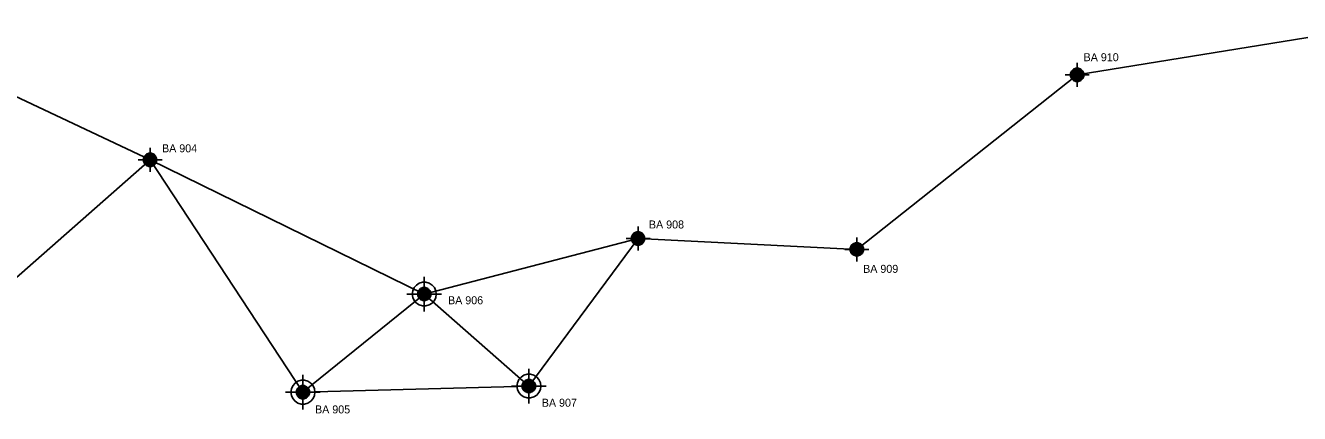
# Model space of a CAD drawing. Extents: x -346533 to -339969, y -1273090 to -1271585.
# Drawn here: x -344688 to -343494, y -1272964 to -1272600 of the extents above; entities that cross this region are included whole.
import ezdxf

# ---------------------------------------------------------------- set-up
doc = ezdxf.new("R2010")
doc.units = 0
for name, color, linetype in [('BP_11', 7, 'Continuous'), ('BP_12', 7, 'Continuous'), ('BP_14', 7, 'Continuous')]:
    doc.layers.add(name, color=color, linetype=linetype)

msp = doc.modelspace()

# ---------------------------------------------------------------- linework, layer by layer
at = {"layer": 'BP_11'}
for points in [[(-343702.54, -1272658), (-343702.54, -1272651.65), (-343702.54, -1272645.3), (-343702.54, -1272638.95), (-343702.54, -1272635.5)], [(-343713.79, -1272646.75), (-343707.44, -1272646.75), (-343701.09, -1272646.75), (-343694.74, -1272646.75), (-343691.29, -1272646.75)], [(-343702.54, -1272640.6), (-343701.34, -1272640.6), (-343699.09, -1272641.55), (-343697.39, -1272643.25), (-343696.44, -1272645.5), (-343696.44, -1272647.95), (-343697.39, -1272650.2), (-343699.09, -1272651.9), (-343701.34, -1272652.85), (-343703.79, -1272652.85), (-343706.04, -1272651.9), (-343707.74, -1272650.2), (-343708.69, -1272647.95), (-343708.69, -1272645.5), (-343707.74, -1272643.25), (-343706.04, -1272641.55), (-343703.79, -1272640.6), (-343702.59, -1272640.6), (-343700.79, -1272640.95), (-343704.39, -1272640.95), (-343705.19, -1272641.35), (-343699.99, -1272641.35), (-343699.19, -1272641.75), (-343705.54, -1272641.75), (-343705.99, -1272641.75), (-343706.39, -1272642.15), (-343700.04, -1272642.15), (-343698.79, -1272642.15), (-343698.39, -1272642.55), (-343704.74, -1272642.55), (-343706.79, -1272642.55), (-343707.19, -1272642.95), (-343700.84, -1272642.95), (-343697.99, -1272642.95), (-343697.59, -1272643.35), (-343703.94, -1272643.35), (-343707.59, -1272643.35), (-343707.59, -1272643.75), (-343701.24, -1272643.75), (-343697.59, -1272643.75), (-343697.19, -1272644.15), (-343703.54, -1272644.15), (-343707.99, -1272644.15), (-343707.99, -1272644.55), (-343701.64, -1272644.55), (-343697.19, -1272644.55), (-343696.79, -1272644.95), (-343703.14, -1272644.95), (-343708.39, -1272644.95), (-343708.39, -1272645.35), (-343702.04, -1272645.35), (-343696.79, -1272645.35), (-343696.79, -1272645.75), (-343703.14, -1272645.75), (-343708.39, -1272645.75), (-343708.39, -1272646.15), (-343702.04, -1272646.15), (-343696.79, -1272646.15), (-343696.79, -1272646.55), (-343703.14, -1272646.55), (-343708.39, -1272646.55), (-343708.39, -1272646.95), (-343702.04, -1272646.95), (-343696.79, -1272646.95), (-343696.79, -1272647.35), (-343703.14, -1272647.35), (-343708.39, -1272647.35), (-343708.39, -1272647.75), (-343702.04, -1272647.75), (-343696.79, -1272647.75), (-343696.79, -1272648.15), (-343703.14, -1272648.15), (-343708.39, -1272648.15), (-343708.39, -1272648.55), (-343702.04, -1272648.55), (-343696.79, -1272648.55), (-343697.19, -1272648.95), (-343703.54, -1272648.95), (-343707.99, -1272648.95), (-343707.99, -1272649.35), (-343701.64, -1272649.35), (-343697.19, -1272649.35), (-343697.59, -1272649.75), (-343703.94, -1272649.75), (-343707.59, -1272649.75), (-343707.59, -1272650.15), (-343701.24, -1272650.15), (-343697.59, -1272650.15), (-343697.99, -1272650.55), (-343704.34, -1272650.55), (-343707.19, -1272650.55), (-343706.79, -1272650.95), (-343700.44, -1272650.95), (-343698.39, -1272650.95), (-343698.79, -1272651.35), (-343705.14, -1272651.35), (-343706.39, -1272651.35), (-343705.99, -1272651.75), (-343699.64, -1272651.75), (-343699.19, -1272651.75)], [(-343699.19, -1272651.75), (-343699.99, -1272652.15), (-343705.19, -1272652.15), (-343704.39, -1272652.55), (-343700.79, -1272652.55)], [(-344571.36, -1272720.27), (-344570.16, -1272720.27), (-344567.91, -1272721.22), (-344566.21, -1272722.92), (-344565.26, -1272725.17), (-344565.26, -1272727.62), (-344566.21, -1272729.87), (-344567.91, -1272731.57), (-344570.16, -1272732.52), (-344572.61, -1272732.52), (-344574.86, -1272731.57), (-344576.56, -1272729.87), (-344577.51, -1272727.62), (-344577.51, -1272725.17), (-344576.56, -1272722.92), (-344574.86, -1272721.22), (-344572.61, -1272720.27), (-344571.41, -1272720.27), (-344569.61, -1272720.62), (-344573.21, -1272720.62), (-344574.01, -1272721.02), (-344568.81, -1272721.02), (-344568.01, -1272721.42), (-344574.36, -1272721.42), (-344574.81, -1272721.42), (-344575.21, -1272721.82), (-344568.86, -1272721.82), (-344567.61, -1272721.82), (-344567.21, -1272722.22), (-344573.56, -1272722.22), (-344575.61, -1272722.22), (-344576.01, -1272722.62), (-344569.66, -1272722.62), (-344566.81, -1272722.62), (-344566.41, -1272723.02), (-344572.76, -1272723.02), (-344576.41, -1272723.02), (-344576.41, -1272723.42), (-344570.06, -1272723.42), (-344566.41, -1272723.42), (-344566.01, -1272723.82), (-344572.36, -1272723.82), (-344576.81, -1272723.82), (-344576.81, -1272724.22), (-344570.46, -1272724.22), (-344566.01, -1272724.22), (-344565.61, -1272724.62), (-344571.96, -1272724.62), (-344577.21, -1272724.62), (-344577.21, -1272725.02), (-344570.86, -1272725.02), (-344565.61, -1272725.02), (-344565.61, -1272725.42), (-344571.96, -1272725.42), (-344577.21, -1272725.42), (-344577.21, -1272725.82), (-344570.86, -1272725.82), (-344565.61, -1272725.82), (-344565.61, -1272726.22), (-344571.96, -1272726.22), (-344577.21, -1272726.22), (-344577.21, -1272726.62), (-344570.86, -1272726.62), (-344565.61, -1272726.62), (-344565.61, -1272727.02), (-344571.96, -1272727.02), (-344577.21, -1272727.02), (-344577.21, -1272727.42), (-344570.86, -1272727.42), (-344565.61, -1272727.42), (-344565.61, -1272727.82), (-344571.96, -1272727.82), (-344577.21, -1272727.82), (-344577.21, -1272728.22), (-344570.86, -1272728.22), (-344565.61, -1272728.22), (-344566.01, -1272728.62), (-344572.36, -1272728.62), (-344576.81, -1272728.62), (-344576.81, -1272729.02), (-344570.46, -1272729.02), (-344566.01, -1272729.02), (-344566.41, -1272729.42), (-344572.76, -1272729.42), (-344576.41, -1272729.42), (-344576.41, -1272729.82), (-344570.06, -1272729.82), (-344566.41, -1272729.82), (-344566.81, -1272730.22), (-344573.16, -1272730.22), (-344576.01, -1272730.22), (-344575.61, -1272730.62), (-344569.26, -1272730.62), (-344567.21, -1272730.62), (-344567.61, -1272731.02), (-344573.96, -1272731.02), (-344575.21, -1272731.02), (-344574.81, -1272731.42), (-344568.46, -1272731.42), (-344568.01, -1272731.42)], [(-344571.36, -1272737.67), (-344571.36, -1272731.32), (-344571.36, -1272724.97), (-344571.36, -1272718.62), (-344571.36, -1272715.17)], [(-344582.61, -1272726.42), (-344576.26, -1272726.42), (-344569.91, -1272726.42), (-344563.56, -1272726.42), (-344560.11, -1272726.42)], [(-344568.01, -1272731.42), (-344568.81, -1272731.82), (-344574.01, -1272731.82), (-344573.21, -1272732.22), (-344569.61, -1272732.22)], [(-344114.12, -1272811.38), (-344114.12, -1272805.03), (-344114.12, -1272798.68), (-344114.12, -1272792.33), (-344114.12, -1272788.88)], [(-344125.37, -1272800.13), (-344119.02, -1272800.13), (-344112.67, -1272800.13), (-344106.32, -1272800.13), (-344102.87, -1272800.13)], [(-344114.12, -1272793.98), (-344112.92, -1272793.98), (-344110.67, -1272794.93), (-344108.97, -1272796.63), (-344108.02, -1272798.88), (-344108.02, -1272801.33), (-344108.97, -1272803.58), (-344110.67, -1272805.28), (-344112.92, -1272806.23), (-344115.37, -1272806.23), (-344117.62, -1272805.28), (-344119.32, -1272803.58), (-344120.27, -1272801.33), (-344120.27, -1272798.88), (-344119.32, -1272796.63), (-344117.62, -1272794.93), (-344115.37, -1272793.98), (-344114.17, -1272793.98), (-344112.37, -1272794.33), (-344115.97, -1272794.33), (-344116.77, -1272794.73), (-344111.57, -1272794.73), (-344110.77, -1272795.13), (-344117.12, -1272795.13), (-344117.57, -1272795.13), (-344117.97, -1272795.53), (-344111.62, -1272795.53), (-344110.37, -1272795.53), (-344109.97, -1272795.93), (-344116.32, -1272795.93), (-344118.37, -1272795.93), (-344118.77, -1272796.33), (-344112.42, -1272796.33), (-344109.57, -1272796.33), (-344109.17, -1272796.73), (-344115.52, -1272796.73), (-344119.17, -1272796.73), (-344119.17, -1272797.13), (-344112.82, -1272797.13), (-344109.17, -1272797.13), (-344108.77, -1272797.53), (-344115.12, -1272797.53), (-344119.57, -1272797.53), (-344119.57, -1272797.93), (-344113.22, -1272797.93), (-344108.77, -1272797.93), (-344108.37, -1272798.33), (-344114.72, -1272798.33), (-344119.97, -1272798.33), (-344119.97, -1272798.73), (-344113.62, -1272798.73), (-344108.37, -1272798.73), (-344108.37, -1272799.13), (-344114.72, -1272799.13), (-344119.97, -1272799.13), (-344119.97, -1272799.53), (-344113.62, -1272799.53), (-344108.37, -1272799.53), (-344108.37, -1272799.93), (-344114.72, -1272799.93), (-344119.97, -1272799.93), (-344119.97, -1272800.33), (-344113.62, -1272800.33), (-344108.37, -1272800.33), (-344108.37, -1272800.73), (-344114.72, -1272800.73), (-344119.97, -1272800.73), (-344119.97, -1272801.13), (-344113.62, -1272801.13), (-344108.37, -1272801.13), (-344108.37, -1272801.53), (-344114.72, -1272801.53), (-344119.97, -1272801.53), (-344119.97, -1272801.93), (-344113.62, -1272801.93), (-344108.37, -1272801.93), (-344108.77, -1272802.33), (-344115.12, -1272802.33), (-344119.57, -1272802.33), (-344119.57, -1272802.73), (-344113.22, -1272802.73), (-344108.77, -1272802.73), (-344109.17, -1272803.13), (-344115.52, -1272803.13), (-344119.17, -1272803.13), (-344119.17, -1272803.53), (-344112.82, -1272803.53), (-344109.17, -1272803.53), (-344109.57, -1272803.93), (-344115.92, -1272803.93), (-344118.77, -1272803.93), (-344118.37, -1272804.33), (-344112.02, -1272804.33), (-344109.97, -1272804.33), (-344110.37, -1272804.73), (-344116.72, -1272804.73), (-344117.97, -1272804.73), (-344117.57, -1272805.13), (-344111.22, -1272805.13), (-344110.77, -1272805.13)], [(-344110.77, -1272805.13), (-344111.57, -1272805.53), (-344116.77, -1272805.53), (-344115.97, -1272805.93), (-344112.37, -1272805.93)], [(-343909.01, -1272804.12), (-343907.81, -1272804.12), (-343905.56, -1272805.07), (-343903.86, -1272806.77), (-343902.91, -1272809.02), (-343902.91, -1272811.47), (-343903.86, -1272813.72), (-343905.56, -1272815.42), (-343907.81, -1272816.37), (-343910.26, -1272816.37), (-343912.51, -1272815.42), (-343914.21, -1272813.72), (-343915.16, -1272811.47), (-343915.16, -1272809.02), (-343914.21, -1272806.77), (-343912.51, -1272805.07), (-343910.26, -1272804.12), (-343909.06, -1272804.12), (-343907.26, -1272804.47), (-343910.86, -1272804.47), (-343911.66, -1272804.87), (-343906.46, -1272804.87), (-343905.66, -1272805.27), (-343912.01, -1272805.27), (-343912.46, -1272805.27), (-343912.86, -1272805.67), (-343906.51, -1272805.67), (-343905.26, -1272805.67), (-343904.86, -1272806.07), (-343911.21, -1272806.07), (-343913.26, -1272806.07), (-343913.66, -1272806.47), (-343907.31, -1272806.47), (-343904.46, -1272806.47), (-343904.06, -1272806.87), (-343910.41, -1272806.87), (-343914.06, -1272806.87), (-343914.06, -1272807.27), (-343907.71, -1272807.27), (-343904.06, -1272807.27), (-343903.66, -1272807.67), (-343910.01, -1272807.67), (-343914.46, -1272807.67), (-343914.46, -1272808.07), (-343908.11, -1272808.07), (-343903.66, -1272808.07), (-343903.26, -1272808.47), (-343909.61, -1272808.47), (-343914.86, -1272808.47), (-343914.86, -1272808.87), (-343908.51, -1272808.87), (-343903.26, -1272808.87), (-343903.26, -1272809.27), (-343909.61, -1272809.27), (-343914.86, -1272809.27), (-343914.86, -1272809.67), (-343908.51, -1272809.67), (-343903.26, -1272809.67), (-343903.26, -1272810.07), (-343909.61, -1272810.07), (-343914.86, -1272810.07), (-343914.86, -1272810.47), (-343908.51, -1272810.47), (-343903.26, -1272810.47), (-343903.26, -1272810.87), (-343909.61, -1272810.87), (-343914.86, -1272810.87), (-343914.86, -1272811.27), (-343908.51, -1272811.27), (-343903.26, -1272811.27), (-343903.26, -1272811.67), (-343909.61, -1272811.67), (-343914.86, -1272811.67), (-343914.86, -1272812.07), (-343908.51, -1272812.07), (-343903.26, -1272812.07), (-343903.66, -1272812.47), (-343910.01, -1272812.47), (-343914.46, -1272812.47), (-343914.46, -1272812.87), (-343908.11, -1272812.87), (-343903.66, -1272812.87), (-343904.06, -1272813.27), (-343910.41, -1272813.27), (-343914.06, -1272813.27), (-343914.06, -1272813.67), (-343907.71, -1272813.67), (-343904.06, -1272813.67), (-343904.46, -1272814.07), (-343910.81, -1272814.07), (-343913.66, -1272814.07), (-343913.26, -1272814.47), (-343906.91, -1272814.47), (-343904.86, -1272814.47), (-343905.26, -1272814.87), (-343911.61, -1272814.87), (-343912.86, -1272814.87), (-343912.46, -1272815.27), (-343906.11, -1272815.27), (-343905.66, -1272815.27)], [(-343909.01, -1272821.52), (-343909.01, -1272815.17), (-343909.01, -1272808.82), (-343909.01, -1272802.47), (-343909.01, -1272799.02)], [(-343920.26, -1272810.27), (-343913.91, -1272810.27), (-343907.56, -1272810.27), (-343901.21, -1272810.27), (-343897.76, -1272810.27)], [(-343905.66, -1272815.27), (-343906.46, -1272815.67), (-343911.66, -1272815.67), (-343910.86, -1272816.07), (-343907.26, -1272816.07)], [(-344314.42, -1272868.49), (-344314.42, -1272862.14), (-344314.42, -1272855.79), (-344314.42, -1272849.44), (-344314.42, -1272843.09), (-344314.42, -1272836.74), (-344314.42, -1272835.99)], [(-344330.67, -1272852.24), (-344324.32, -1272852.24), (-344317.97, -1272852.24), (-344311.62, -1272852.24), (-344305.27, -1272852.24), (-344298.92, -1272852.24), (-344298.17, -1272852.24)], [(-344314.42, -1272846.09), (-344313.22, -1272846.09), (-344310.97, -1272847.04), (-344309.27, -1272848.74), (-344308.32, -1272850.99), (-344308.32, -1272853.44), (-344309.27, -1272855.69), (-344310.97, -1272857.39), (-344313.22, -1272858.34), (-344315.67, -1272858.34), (-344317.92, -1272857.39), (-344319.62, -1272855.69), (-344320.57, -1272853.44), (-344320.57, -1272850.99), (-344319.62, -1272848.74), (-344317.92, -1272847.04), (-344315.67, -1272846.09), (-344314.47, -1272846.09), (-344312.67, -1272846.44), (-344316.27, -1272846.44), (-344317.07, -1272846.84), (-344311.87, -1272846.84), (-344311.07, -1272847.24), (-344317.42, -1272847.24), (-344317.87, -1272847.24), (-344318.27, -1272847.64), (-344311.92, -1272847.64), (-344310.67, -1272847.64), (-344310.27, -1272848.04), (-344316.62, -1272848.04), (-344318.67, -1272848.04), (-344319.07, -1272848.44), (-344312.72, -1272848.44), (-344309.87, -1272848.44), (-344309.47, -1272848.84), (-344315.82, -1272848.84), (-344319.47, -1272848.84), (-344319.47, -1272849.24), (-344313.12, -1272849.24), (-344309.47, -1272849.24), (-344309.07, -1272849.64), (-344315.42, -1272849.64), (-344319.87, -1272849.64), (-344319.87, -1272850.04), (-344313.52, -1272850.04), (-344309.07, -1272850.04), (-344309.07, -1272850.44), (-344315.42, -1272850.44), (-344319.87, -1272850.44), (-344320.27, -1272850.84), (-344313.92, -1272850.84), (-344308.67, -1272850.84), (-344308.67, -1272851.24), (-344315.02, -1272851.24), (-344320.27, -1272851.24), (-344320.27, -1272851.64), (-344313.92, -1272851.64), (-344308.67, -1272851.64), (-344308.67, -1272852.04), (-344315.02, -1272852.04), (-344320.27, -1272852.04), (-344320.27, -1272852.44), (-344313.92, -1272852.44), (-344308.67, -1272852.44), (-344308.67, -1272852.84), (-344315.02, -1272852.84), (-344320.27, -1272852.84), (-344320.27, -1272853.24), (-344313.92, -1272853.24), (-344308.67, -1272853.24), (-344308.67, -1272853.64), (-344315.02, -1272853.64), (-344320.27, -1272853.64), (-344320.27, -1272854.04), (-344313.92, -1272854.04), (-344308.67, -1272854.04), (-344309.07, -1272854.44), (-344315.42, -1272854.44), (-344319.87, -1272854.44), (-344319.87, -1272854.84), (-344313.52, -1272854.84), (-344309.07, -1272854.84), (-344309.47, -1272855.24), (-344315.82, -1272855.24), (-344319.47, -1272855.24), (-344319.47, -1272855.64), (-344313.12, -1272855.64), (-344309.47, -1272855.64), (-344309.87, -1272856.04), (-344316.22, -1272856.04), (-344319.07, -1272856.04), (-344318.67, -1272856.44), (-344312.32, -1272856.44), (-344310.27, -1272856.44), (-344310.67, -1272856.84), (-344317.02, -1272856.84), (-344318.27, -1272856.84), (-344317.87, -1272857.24), (-344311.52, -1272857.24), (-344311.07, -1272857.24)], [(-344311.07, -1272857.24), (-344311.87, -1272857.64), (-344317.07, -1272857.64), (-344316.27, -1272858.04), (-344312.67, -1272858.04)], [(-344216.4, -1272954.74), (-344216.4, -1272948.39), (-344216.4, -1272942.04), (-344216.4, -1272935.69), (-344216.4, -1272929.34), (-344216.4, -1272922.99), (-344216.4, -1272922.24)], [(-344428.13, -1272960.43), (-344428.13, -1272954.08), (-344428.13, -1272947.73), (-344428.13, -1272941.38), (-344428.13, -1272935.03), (-344428.13, -1272928.68), (-344428.13, -1272927.93)], [(-344216.4, -1272932.34), (-344215.2, -1272932.34), (-344212.95, -1272933.29), (-344211.25, -1272934.99), (-344210.3, -1272937.24), (-344210.3, -1272939.69), (-344211.25, -1272941.94), (-344212.95, -1272943.64), (-344215.2, -1272944.59), (-344217.65, -1272944.59), (-344219.9, -1272943.64), (-344221.6, -1272941.94), (-344222.55, -1272939.69), (-344222.55, -1272937.24), (-344221.6, -1272934.99), (-344219.9, -1272933.29), (-344217.65, -1272932.34), (-344216.45, -1272932.34), (-344214.65, -1272932.69), (-344218.25, -1272932.69), (-344219.05, -1272933.09), (-344213.85, -1272933.09), (-344213.05, -1272933.49), (-344219.4, -1272933.49), (-344219.85, -1272933.49), (-344220.25, -1272933.89), (-344213.9, -1272933.89), (-344212.65, -1272933.89), (-344212.25, -1272934.29), (-344218.6, -1272934.29), (-344220.65, -1272934.29), (-344221.05, -1272934.69), (-344214.7, -1272934.69), (-344211.85, -1272934.69), (-344211.45, -1272935.09), (-344217.8, -1272935.09), (-344221.45, -1272935.09), (-344221.45, -1272935.49), (-344215.1, -1272935.49), (-344211.45, -1272935.49), (-344211.05, -1272935.89), (-344217.4, -1272935.89), (-344221.85, -1272935.89), (-344221.85, -1272936.29), (-344215.5, -1272936.29), (-344211.05, -1272936.29), (-344211.05, -1272936.69), (-344217.4, -1272936.69), (-344221.85, -1272936.69), (-344222.25, -1272937.09), (-344215.9, -1272937.09), (-344210.65, -1272937.09), (-344210.65, -1272937.49), (-344217, -1272937.49), (-344222.25, -1272937.49), (-344222.25, -1272937.89), (-344215.9, -1272937.89), (-344210.65, -1272937.89), (-344210.65, -1272938.29), (-344217, -1272938.29), (-344222.25, -1272938.29), (-344222.25, -1272938.69), (-344215.9, -1272938.69), (-344210.65, -1272938.69), (-344210.65, -1272939.09), (-344217, -1272939.09), (-344222.25, -1272939.09), (-344222.25, -1272939.49), (-344215.9, -1272939.49), (-344210.65, -1272939.49), (-344210.65, -1272939.89), (-344217, -1272939.89), (-344222.25, -1272939.89), (-344222.25, -1272940.29), (-344215.9, -1272940.29), (-344210.65, -1272940.29), (-344211.05, -1272940.69), (-344217.4, -1272940.69), (-344221.85, -1272940.69), (-344221.85, -1272941.09), (-344215.5, -1272941.09), (-344211.05, -1272941.09), (-344211.45, -1272941.49), (-344217.8, -1272941.49), (-344221.45, -1272941.49), (-344221.45, -1272941.89), (-344215.1, -1272941.89), (-344211.45, -1272941.89), (-344211.85, -1272942.29), (-344218.2, -1272942.29), (-344221.05, -1272942.29), (-344220.65, -1272942.69), (-344214.3, -1272942.69), (-344212.25, -1272942.69), (-344212.65, -1272943.09), (-344219, -1272943.09), (-344220.25, -1272943.09), (-344219.85, -1272943.49), (-344213.5, -1272943.49), (-344213.05, -1272943.49)], [(-344444.38, -1272944.18), (-344438.03, -1272944.18), (-344431.68, -1272944.18), (-344425.33, -1272944.18), (-344418.98, -1272944.18), (-344412.63, -1272944.18), (-344411.88, -1272944.18)], [(-344428.13, -1272938.03), (-344426.93, -1272938.03), (-344424.68, -1272938.98), (-344422.98, -1272940.68), (-344422.03, -1272942.93), (-344422.03, -1272945.38), (-344422.98, -1272947.63), (-344424.68, -1272949.33), (-344426.93, -1272950.28), (-344429.38, -1272950.28), (-344431.63, -1272949.33), (-344433.33, -1272947.63), (-344434.28, -1272945.38), (-344434.28, -1272942.93), (-344433.33, -1272940.68), (-344431.63, -1272938.98), (-344429.38, -1272938.03), (-344428.18, -1272938.03), (-344426.38, -1272938.38), (-344429.98, -1272938.38), (-344430.78, -1272938.78), (-344425.58, -1272938.78), (-344424.78, -1272939.18), (-344431.13, -1272939.18), (-344431.58, -1272939.18), (-344431.98, -1272939.58), (-344425.63, -1272939.58), (-344424.38, -1272939.58), (-344423.98, -1272939.98), (-344430.33, -1272939.98), (-344432.38, -1272939.98), (-344432.78, -1272940.38), (-344426.43, -1272940.38), (-344423.58, -1272940.38), (-344423.18, -1272940.78), (-344429.53, -1272940.78), (-344433.18, -1272940.78), (-344433.18, -1272941.18), (-344426.83, -1272941.18), (-344423.18, -1272941.18), (-344422.78, -1272941.58), (-344429.13, -1272941.58), (-344433.58, -1272941.58), (-344433.58, -1272941.98), (-344427.23, -1272941.98), (-344422.78, -1272941.98), (-344422.78, -1272942.38), (-344429.13, -1272942.38), (-344433.58, -1272942.38), (-344433.98, -1272942.78), (-344427.63, -1272942.78), (-344422.38, -1272942.78), (-344422.38, -1272943.18), (-344428.73, -1272943.18), (-344433.98, -1272943.18), (-344433.98, -1272943.58), (-344427.63, -1272943.58), (-344422.38, -1272943.58), (-344422.38, -1272943.98), (-344428.73, -1272943.98), (-344433.98, -1272943.98), (-344433.98, -1272944.38), (-344427.63, -1272944.38), (-344422.38, -1272944.38), (-344422.38, -1272944.78), (-344428.73, -1272944.78), (-344433.98, -1272944.78), (-344433.98, -1272945.18), (-344427.63, -1272945.18), (-344422.38, -1272945.18), (-344422.38, -1272945.58), (-344428.73, -1272945.58), (-344433.98, -1272945.58), (-344433.98, -1272945.98), (-344427.63, -1272945.98), (-344422.38, -1272945.98), (-344422.78, -1272946.38), (-344429.13, -1272946.38), (-344433.58, -1272946.38), (-344433.58, -1272946.78), (-344427.23, -1272946.78), (-344422.78, -1272946.78), (-344423.18, -1272947.18), (-344429.53, -1272947.18), (-344433.18, -1272947.18), (-344433.18, -1272947.58), (-344426.83, -1272947.58), (-344423.18, -1272947.58), (-344423.58, -1272947.98), (-344429.93, -1272947.98), (-344432.78, -1272947.98), (-344432.38, -1272948.38), (-344426.03, -1272948.38), (-344423.98, -1272948.38), (-344424.38, -1272948.78), (-344430.73, -1272948.78), (-344431.98, -1272948.78), (-344431.58, -1272949.18), (-344425.23, -1272949.18), (-344424.78, -1272949.18)], [(-344232.65, -1272938.49), (-344226.3, -1272938.49), (-344219.95, -1272938.49), (-344213.6, -1272938.49), (-344207.25, -1272938.49), (-344200.9, -1272938.49), (-344200.15, -1272938.49)], [(-344213.05, -1272943.49), (-344213.85, -1272943.89), (-344219.05, -1272943.89), (-344218.25, -1272944.29), (-344214.65, -1272944.29)], [(-344424.78, -1272949.18), (-344425.58, -1272949.58), (-344430.78, -1272949.58), (-344429.98, -1272949.98), (-344426.38, -1272949.98)]]:
    msp.add_lwpolyline(points, dxfattribs=at)
for points in [[(-343701.34, -1272640.6), (-343699.09, -1272641.55), (-343697.39, -1272643.25), (-343696.44, -1272645.5), (-343696.44, -1272647.95), (-343697.39, -1272650.2), (-343699.09, -1272651.9), (-343701.34, -1272652.85), (-343703.79, -1272652.85), (-343706.04, -1272651.9), (-343707.74, -1272650.2), (-343708.69, -1272647.95), (-343708.69, -1272645.5), (-343707.74, -1272643.25), (-343706.04, -1272641.55), (-343703.79, -1272640.6)], [(-344570.16, -1272720.27), (-344567.91, -1272721.22), (-344566.21, -1272722.92), (-344565.26, -1272725.17), (-344565.26, -1272727.62), (-344566.21, -1272729.87), (-344567.91, -1272731.57), (-344570.16, -1272732.52), (-344572.61, -1272732.52), (-344574.86, -1272731.57), (-344576.56, -1272729.87), (-344577.51, -1272727.62), (-344577.51, -1272725.17), (-344576.56, -1272722.92), (-344574.86, -1272721.22), (-344572.61, -1272720.27)], [(-344112.92, -1272793.98), (-344110.67, -1272794.93), (-344108.97, -1272796.63), (-344108.02, -1272798.88), (-344108.02, -1272801.33), (-344108.97, -1272803.58), (-344110.67, -1272805.28), (-344112.92, -1272806.23), (-344115.37, -1272806.23), (-344117.62, -1272805.28), (-344119.32, -1272803.58), (-344120.27, -1272801.33), (-344120.27, -1272798.88), (-344119.32, -1272796.63), (-344117.62, -1272794.93), (-344115.37, -1272793.98)], [(-343907.81, -1272804.12), (-343905.56, -1272805.07), (-343903.86, -1272806.77), (-343902.91, -1272809.02), (-343902.91, -1272811.47), (-343903.86, -1272813.72), (-343905.56, -1272815.42), (-343907.81, -1272816.37), (-343910.26, -1272816.37), (-343912.51, -1272815.42), (-343914.21, -1272813.72), (-343915.16, -1272811.47), (-343915.16, -1272809.02), (-343914.21, -1272806.77), (-343912.51, -1272805.07), (-343910.26, -1272804.12)], [(-344312.82, -1272841.09), (-344309.77, -1272841.99), (-344307.07, -1272843.74), (-344304.97, -1272846.14), (-344303.62, -1272849.04), (-344303.17, -1272852.19), (-344303.62, -1272855.34), (-344304.97, -1272858.24), (-344307.07, -1272860.64), (-344309.77, -1272862.39), (-344312.82, -1272863.29), (-344316.02, -1272863.29), (-344319.07, -1272862.39), (-344321.77, -1272860.64), (-344323.87, -1272858.24), (-344325.22, -1272855.34), (-344325.67, -1272852.19), (-344325.22, -1272849.04), (-344323.87, -1272846.14), (-344321.77, -1272843.74), (-344319.07, -1272841.99), (-344316.02, -1272841.09)], [(-344426.53, -1272933.03), (-344423.48, -1272933.93), (-344420.78, -1272935.68), (-344418.68, -1272938.08), (-344417.33, -1272940.98), (-344416.88, -1272944.13), (-344417.33, -1272947.28), (-344418.68, -1272950.18), (-344420.78, -1272952.58), (-344423.48, -1272954.33), (-344426.53, -1272955.23), (-344429.73, -1272955.23), (-344432.78, -1272954.33), (-344435.48, -1272952.58), (-344437.58, -1272950.18), (-344438.93, -1272947.28), (-344439.38, -1272944.13), (-344438.93, -1272940.98), (-344437.58, -1272938.08), (-344435.48, -1272935.68), (-344432.78, -1272933.93), (-344429.73, -1272933.03)], [(-344214.8, -1272927.34), (-344211.75, -1272928.24), (-344209.05, -1272929.99), (-344206.95, -1272932.39), (-344205.6, -1272935.29), (-344205.15, -1272938.44), (-344205.6, -1272941.59), (-344206.95, -1272944.49), (-344209.05, -1272946.89), (-344211.75, -1272948.64), (-344214.8, -1272949.54), (-344218, -1272949.54), (-344221.05, -1272948.64), (-344223.75, -1272946.89), (-344225.85, -1272944.49), (-344227.2, -1272941.59), (-344227.65, -1272938.44), (-344227.2, -1272935.29), (-344225.85, -1272932.39), (-344223.75, -1272929.99), (-344221.05, -1272928.24), (-344218, -1272927.34)]]:
    msp.add_lwpolyline(points, close=True, dxfattribs=at)
at = {"layer": 'BP_14'}
for p, q in [((-344837, -1272601.02), (-344571.36, -1272726.42)), ((-343702.54, -1272646.75), (-343417.3, -1272600.45)), ((-343909.01, -1272810.27), (-343702.54, -1272646.75)), ((-344571.36, -1272726.42), (-344761.26, -1272893.27)), ((-344571.36, -1272726.42), (-344314.42, -1272852.24)), ((-344428.13, -1272944.18), (-344571.36, -1272726.42)), ((-344314.42, -1272852.24), (-344114.12, -1272800.13)), ((-344114.12, -1272800.13), (-344216.4, -1272938.49)), ((-344114.12, -1272800.13), (-343909.01, -1272810.27)), ((-344428.13, -1272944.18), (-344314.42, -1272852.24)), ((-344314.42, -1272852.24), (-344216.4, -1272938.49)), ((-344216.4, -1272938.49), (-344428.13, -1272944.18))]:
    msp.add_line(p, q, dxfattribs=at)

# ---------------------------------------------------------------- texts
at = {"layer": 'BP_12'}
for s, p in [('BA 910', (-343696.54, -1272633.94)), ('BA 904', (-344560.17, -1272719.32)), ('BA 908', (-344103.9, -1272790.71)), ('BA 909', (-343903.16, -1272832.29)), ('BA 906', (-344292.15, -1272861.74)), ('BA 905', (-344416.78, -1272964.04)), ('BA 907', (-344204.28, -1272957.78))]:
    msp.add_text(s, height=7.5, dxfattribs=at).set_placement(p)

doc.saveas('drawing.dxf')
